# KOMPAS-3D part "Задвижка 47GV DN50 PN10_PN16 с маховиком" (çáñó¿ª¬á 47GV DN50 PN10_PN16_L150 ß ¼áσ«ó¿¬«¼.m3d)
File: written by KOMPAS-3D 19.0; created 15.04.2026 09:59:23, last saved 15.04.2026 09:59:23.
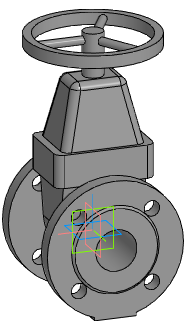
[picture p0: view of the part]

Document properties: Автор: Евгений; Полное имя файла: Z:\3.Личные\kachalov\3d для проектировщиков\2.1 Тип 47GV, 47GV.Z\Задвижка 47GV_DN40-DN600\stp_Задвижка 47GV\Задвижка 47GV DN50 PN10_PN16_L150 с маховиком.m3d

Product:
- Part/product: Задвижка 47GV DN50 PN10_PN16 с маховиком

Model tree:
1. Операция без истории:1  (labels: Задвижка 47GV DN50 PN10_PN16 с маховиком)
